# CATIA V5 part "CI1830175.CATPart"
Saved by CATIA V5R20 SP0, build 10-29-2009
Part number: CI1830175
Bounding box of the stored display mesh (mm): x -29 to 29, y -24.819 to 220, z -38.561 to 32.978
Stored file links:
  C:\Users\Raffaele\Desktop\3D X SITO CF\BOLEX\19-INCLINED ASSEMBLY REF_CI\CI1830175.CATPart

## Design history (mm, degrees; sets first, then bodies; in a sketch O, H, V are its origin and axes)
Set1
  DatumSurface1 to DatumSurface16 "MANIFOLD_SOLID_BREP #395"
  DatumSurface17 to DatumSurface39 "MANIFOLD_SOLID_BREP #1144"
Body1 (main body)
